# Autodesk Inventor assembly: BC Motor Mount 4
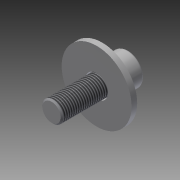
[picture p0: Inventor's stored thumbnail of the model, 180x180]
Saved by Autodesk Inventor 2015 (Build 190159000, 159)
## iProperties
Created: 2007-02
Part Number: BC Motor Mount 4
Document SubType Name: Assembly
Designer: Autodesk, Inc.
Mass: 40.8056 g
Surface Area: 39.4938 cm^2
Volume: 5.19155 cm^3
Density: 7.86 g/cm^3
ClientObjectVersion: 1
Author: Autodesk, Inc.
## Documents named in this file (4)
- C:\Users\Public\Documents\Autodesk\Inventor 2015\Samples\Models\Assemblies\Blower\Blower\Design Accelerator\BC Motor Mount 31.iam
- C:\Users\Public\Documents\Autodesk\Inventor 2015\Samples\Standard Parts\en-US\ANSI B18.22.1\ANSI B18.22.1 - 3_8 - wide - Type B.ipt
- C:\Users\Public\Documents\Autodesk\Inventor 2015\Samples\Standard Parts\en-US\ANSI B18.21.1\ANSI B18.21.1 - 0.375.ipt
- C:\Users\Public\Documents\Autodesk\Inventor 2015\Samples\Standard Parts\en-US\ANSI B18.3(13)\ANSI B18.3 - 3_8-24 UNF - 1(22).ipt
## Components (3 placed, 3 different names)
1. ANSI B18.22.1 - 3/8 - wide - Type B:1
2. ANSI B18.21.1 - 0.375:2
3. ANSI B18.3 - 3/8-24 UNF - 1:3
